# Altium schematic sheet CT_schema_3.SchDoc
size 383 x 218 mm
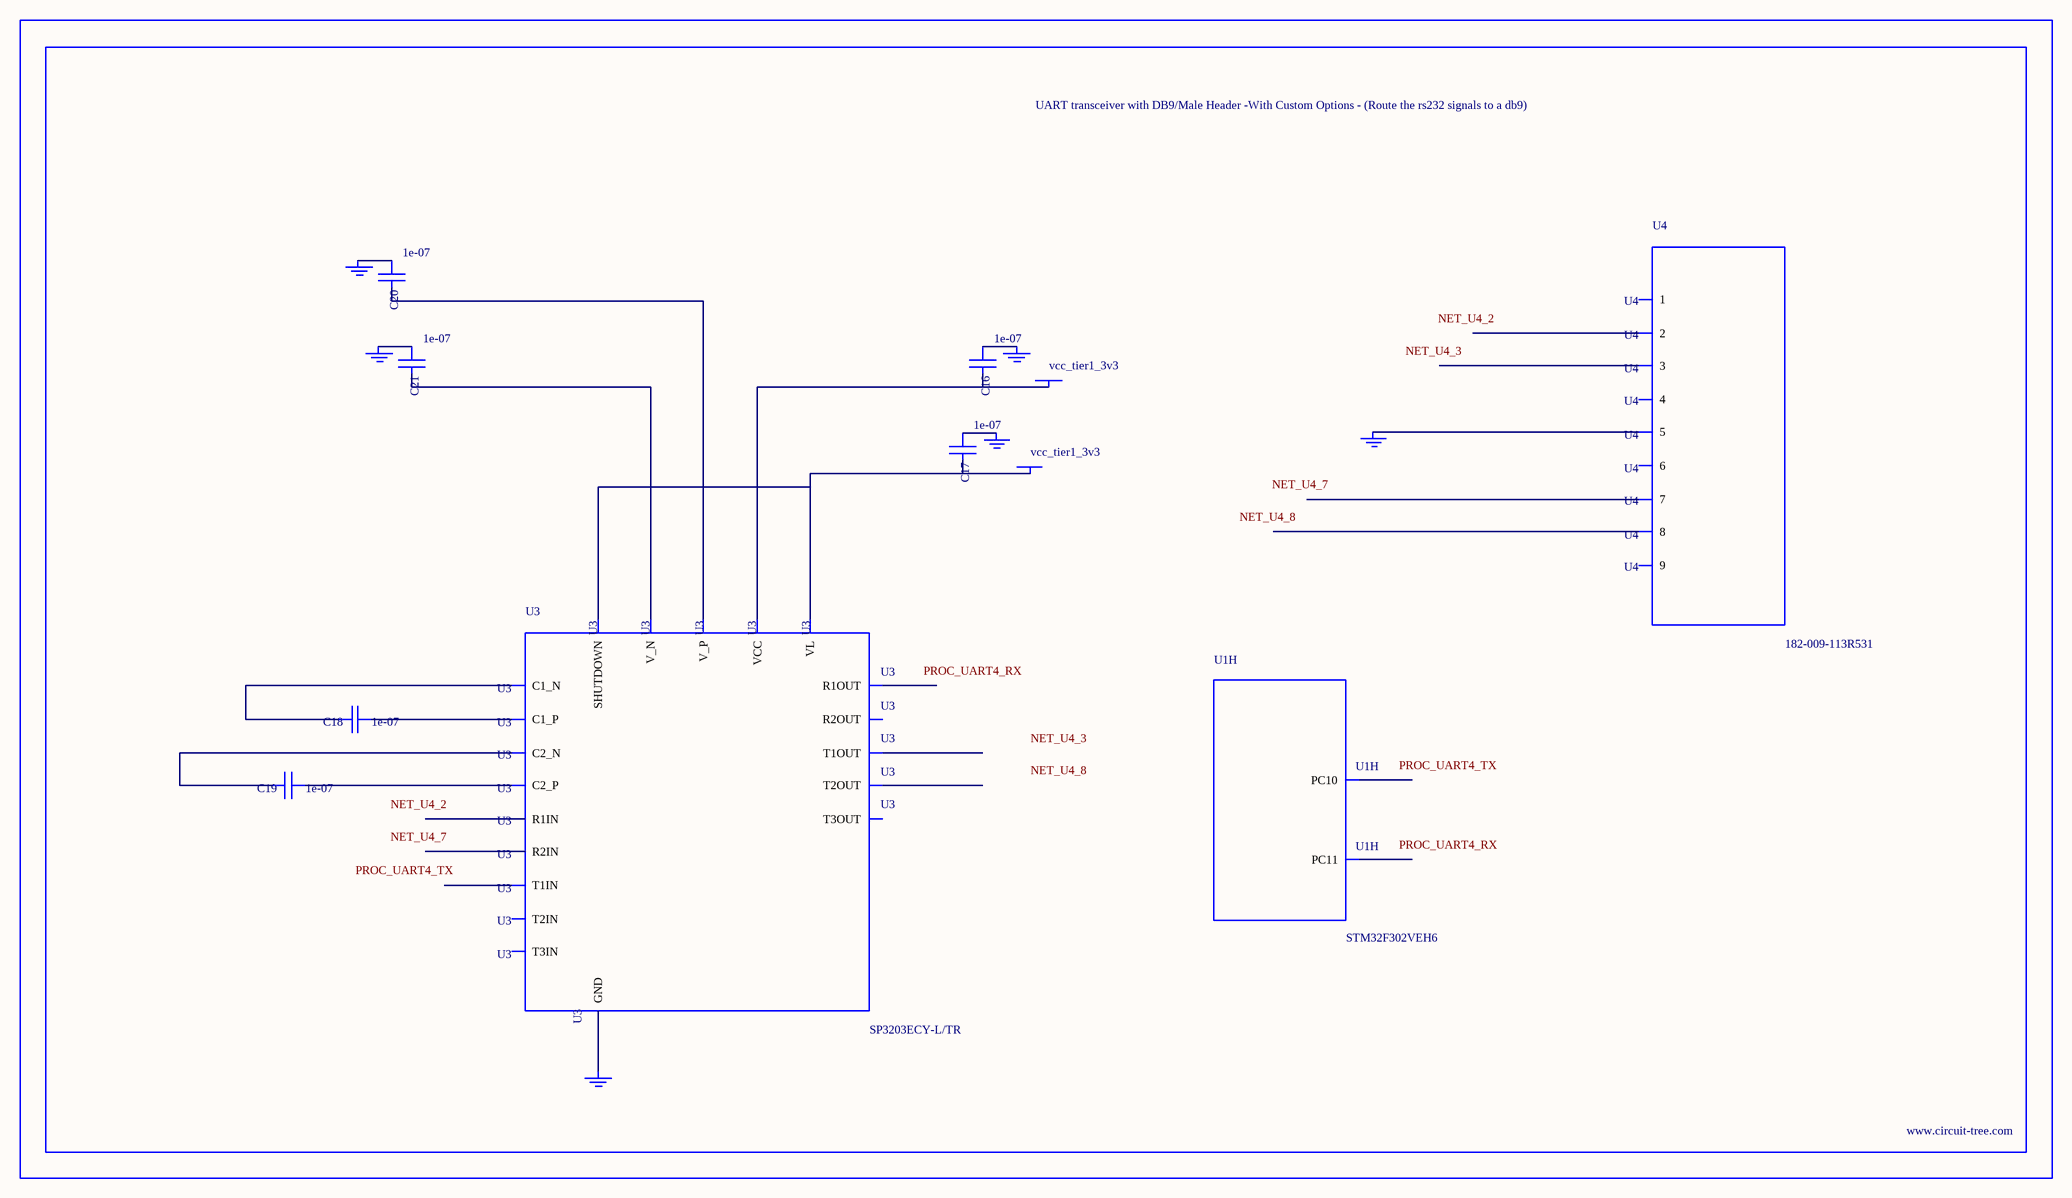
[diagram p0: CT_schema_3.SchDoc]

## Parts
BORDER2  (no value)
C16  1e-07  [C0402]
C17  1e-07  [C0402]
C18  1e-07  [C0402]
C19  1e-07  [C0402]
C20  1e-07  [C0402]
C21  1e-07  [C0402]
GND_INSTANCE_2_0  (no value)
GND_INSTANCE_2_1  (no value)
GND_INSTANCE_2_2  (no value)
GND_INSTANCE_2_3  (no value)
GND_INSTANCE_2_4  (no value)
GND_INSTANCE_2_5  (no value)
POWER_INSTANCE_2_0  vcc_tier1_3v3
POWER_INSTANCE_2_1  vcc_tier1_3v3
U1  STM32F302VEH6  [UFBGA100]  (part H of 9)
U3  SP3203ECY-L/TR  [TSSOP20-I]
U4  182-009-113R531  [182-009-MALE]

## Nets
NetC16_1: C16.1 GND_INSTANCE_2_3.0(GND)
NetC16_2: C16.2 POWER_INSTANCE_2_1.0(PWR) U3.19(VCC)
NetC17_1: C17.1 GND_INSTANCE_2_2.0(GND)
NetC17_2: C17.2 POWER_INSTANCE_2_0.0(PWR) U3.12(VL) U3.20(SHUTDOWN)
NetC18_1: C18.1 U3.1(C1_P)
NetC18_2: C18.2 U3.3(C1_N)
NetC19_1: C19.1 U3.4(C2_P)
NetC19_2: C19.2 U3.5(C2_N)
NetC20_1: C20.1 GND_INSTANCE_2_0.0(GND)
NetC20_2: C20.2 U3.2(V_P)
NetC21_1: C21.1 GND_INSTANCE_2_1.0(GND)
NetC21_2: C21.2 U3.6(V_N)
NetGND_INSTANCE_2_4_0: GND_INSTANCE_2_4.0(GND) U3.18(GND)
NetGND_INSTANCE_2_5_0: GND_INSTANCE_2_5.0(GND) U4.5

Not connected (* = marked no-connect by the designer): U1 B11(PC10) C10(PC11); U3 7(T1IN) 8(T2IN) 9(T3IN) 10(R2OUT) 11(R1OUT) 13(R2IN) 14(R1IN) 15(T3OUT) 16(T2OUT) 17(T1OUT); U4 1 2 3 4 6 7 8 9

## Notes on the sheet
- Labels drawn without touching a wire or pin: NET_U4_2, NET_U4_3, NET_U4_7, NET_U4_8, PROC_UART4_RX, PROC_UART4_TX

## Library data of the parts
BORDER2 = BORDER_PAGE2
C16-C21 = C0402C104K3RACTU
GND_INSTANCE_2_0-GND_INSTANCE_2_5 = GND
POWER_INSTANCE_2_0 POWER_INSTANCE_2_1 = PWR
